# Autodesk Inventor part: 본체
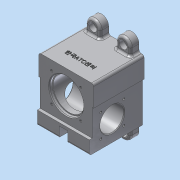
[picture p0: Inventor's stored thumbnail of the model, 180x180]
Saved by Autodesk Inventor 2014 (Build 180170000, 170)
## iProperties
Created: 2024-11
Part Number: 본체
Material: 알루미늄 6061
Document SubType Name: Modeling
Designer: dg
Density: 2.71 g/cm^3
Appearance: 알루미늄 - 평지
Mass: 806.366 g
Surface Area: 539.755 cm^2
Volume: 297.552 cm^3
Author: dg
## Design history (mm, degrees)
sketch "스케치1"
  geometry: L1 (-38, 0)-(38, 0); L2 (38, 0)-(38, -29); L3 (38, -29)-(36, -29); L4 (36, -29)-(36, -85); L5 (36, -85)-(6, -85); L6 (6, -85)-(6, -70); L7 (6, -70)-(-6, -70); L8 (-6, -70)-(-6, -85); L9 (-6, -85)-(-36, -85); L10 (-36, -85)-(-36, -29); L11 (-36, -29)-(-38, -29); L12 (-38, -29)-(-38, 0); 2 further points
  constraints: 24 end point, 10 parallel, 4 equal length, 1 coincident, 1 horizontal, 1 midpoint, 1 perpendicular
  dimensions: "d0" = 76 distance of L1.start L1.end; "d1" = 85 distance between parallel lines of L9 L1; "d2" = 56 distance of L9.end L10.end; "d3" = 15 distance of L7.end L8.end; "d4" = 12 distance of L6.end L7.end; "d5" = 2 distance of L10.end L11.end
extrude "돌출1" new body sketch "스케치1" distance "d6" = 74; taper "d7" = 0 deg
sketch "스케치2"
  geometry: L1 (0, 0)-(66, 0); L2 (66, 0)-(66, 4); L3 (66, 4)-(0, 4); L4 (0, 4)-(0, 0)
  constraints: 8 end point, 2 parallel, 1 horizontal, 1 perpendicular
  dimensions: "d8" = 4 distance of L1.end L2.end; "d9" = 66 distance of L2.end L3.end
extrude "돌출2" cut sketch "스케치2" stored distance "d10" = 74; taper "d11" = 0 deg
sketch "스케치3"
  geometry: L1 (-38, 0)-(38, 0) reference; L2 (36, 85)-(6, 85) reference; L3 (-6, 85)-(-36, 85) reference; L4 (-31, 85)-(-11, 85); L5 (-11, 85)-(-11, 105); L6 (-11, 105)-(-31, 105); L7 (-31, 105)-(-31, 85); L8 (11, 85)-(31, 85); L9 (31, 85)-(31, 105); L10 (31, 105)-(11, 105); L11 (11, 105)-(11, 85); L12 (-31, -20)-(-11, -20); L13 (-11, -20)-(-11, 0); L14 (-11, 0)-(-31, 0); L15 (-31, 0)-(-31, -20); L16 (11, -20)-(31, -20); L17 (31, -20)-(31, 0); L18 (31, 0)-(11, 0); L19 (11, 0)-(11, -20); 5 further points
  constraints: 32 end point, 8 parallel, 6 equal length, 6 midpoint, 4 horizontal, 4 perpendicular, 2 collinear, 2 point on line
  dimensions: "d12" = 20 distance of L5.end L6.end; "d13" = 20 distance of L6.end L4.start; "d14" = 62 distance between parallel lines of L9 L7; "d15" = 31 distance from line of point (0, 0) L7
extrude "돌출3" join sketch "스케치3" distance "d16" = 12; taper "d17" = 0 deg
fillet "모깎기1" dims "d18" = 10
sketch "스케치4" dims "d0" = 76, "d1" = 85, "d2" = 56, "d3" = 15, "d4" = 12, "d5" = 2
  geometry: L1 (0, 0)-(76, 0) reference; 2 further points
  constraints: 1 vertical alignment, 1 other
  dimensions: "d19" = 20 distance from line of point (38, 20) L1
feature "엠보싱1" sketch "스케치4" dims "d0" = 76, "d1" = 85, "d2" = 56, "d3" = 15, "d4" = 12, "d5" = 2, "d20" = 0.5, "d21" = 0
sketch "스케치5"
  geometry: L1 (4, -33)-(70, -33); L2 (4, -66)-(4, -29) reference; L3 (4, 0)-(74, 0) reference; L4 (4, -33)-(4, -9.5); L5 (4, -9.5)-(8, -9.5); L6 (8, -9.5)-(8, -11); L7 (8, -11)-(56, -11); L8 (56, -11)-(56, -15.5); L9 (56, -15.5)-(67, -15.5); L10 (67, -15.5)-(67, -18); L11 (67, -18)-(70, -18); L12 (70, -18)-(70, -33); L13 (0, -85)-(0, -70) reference; 1 further point
  constraints: 20 end point, 6 parallel, 3 perpendicular, 1 horizontal, 1 point on line
  dimensions: "d23" = 33 distance between parallel lines of L1 L3; "d24" = 66 distance of L1.start L1.end; "d25" = 47 diameter of L5 L1; "d26" = 44 diameter of L7 L1; "d27" = 35 diameter of L9 L1; "d28" = 30 diameter of L11 L1; "d29" = 4 distance of L4.end L5.end; "d30" = 56 distance between parallel lines of L13 L8; "d31" = 11 distance of L8.end L9.end
revolve "회전1" sketch "스케치5" stored, may be unused: angle "d32" = 90 deg
sketch "스케치6"
  geometry: L1 (-56, 74)-(0, 74) reference; L2 (-85, 4)-(-85, 74) reference; C1 r 16.5 at (-28, 32); 1 further point
  constraints: 1 centre point
  dimensions: "d33" = 57 distance from line of L2 C1.centre; "d34" = 42 distance from line of C1.centre L1; "d35" = 33 diameter of C1
extrude "돌출4" cut sketch "스케치6" stored distance "d36" = 12; taper "d37" = 0 deg
sketch "스케치7"
  geometry: C1 r 16.5 at (-28, 32) reference; 5 further points
  constraints: 2 horizontal alignment, 2 vertical alignment
  dimensions: "d38" = 32 distance of point (-12, 48) point (-44, 48); "d39" = 32 distance of point (-12, 16) point (-12, 48); "d40" = 16 horizontal distance of point (-12, 48) C1.centre; "d41" = 16 horizontal distance of C1.centre point (-12, 48)
hole "구멍1" sketch "스케치7" at (-44, 48), (-12, 48), (-44, 16), (-12, 16) diameter "d42" = 3.242; stored, may be unused: countersink angle "d46" = 90 deg, drill point angle "d48" = 118 deg; dims "d43" = 8, "d44" = 4, "d45" = 2, "d47" = 10
sketch "스케치8"
  geometry: C1 r 23.5 at (-38, -4) reference; A1 r 28.5 centre (-38, -4) between (-58.153, 16.153) and (-58.153, -24.153); 3 further points
  constraints: 4 point on circle, 2 horizontal alignment, 2 vertical alignment, 1 centre point, 1 coincident
  dimensions: "d49" = 57 diameter of A1; "d50" = 90 deg dimension on C1.centre point (-17.847, -24.153) point (-17.847, 16.153)
hole "구멍2" sketch "스케치8" at (-58.153, 16.153), (-58.153, -24.153), (-17.847, -24.153), (-17.847, 16.153) diameter "d51" = 3.242; stored, may be unused: countersink angle "d55" = 90 deg, drill point angle "d57" = 118 deg; dims "d52" = 8, "d53" = 4, "d54" = 2, "d56" = 10
hole "구멍3" diameter "d60" = 6.6; stored, may be unused: countersink angle "d64" = 90 deg, drill point angle "d66" = 0 deg; dims "d58" = 10, "d59" = 10, "d61" = 8, "d62" = 11, "d63" = 6.6, "d65" = 10
hole "구멍4" diameter "d69" = 6.6; stored, may be unused: countersink angle "d73" = 90 deg, drill point angle "d75" = 0 deg; dims "d67" = 10, "d68" = 10, "d70" = 8, "d71" = 11, "d72" = 6.6, "d74" = 10
hole "구멍5" diameter "d78" = 6.6; stored, may be unused: countersink angle "d82" = 90 deg, drill point angle "d84" = 0 deg; dims "d76" = 10, "d77" = 10, "d79" = 8, "d80" = 11, "d81" = 6.6, "d83" = 10
hole "구멍6" diameter "d87" = 6.6; stored, may be unused: countersink angle "d91" = 90 deg, drill point angle "d93" = 0 deg; dims "d85" = 10, "d86" = 10, "d88" = 8, "d89" = 11, "d90" = 6.6, "d92" = 10
sketch "스케치9"
  geometry: L1 (12, 0)-(0, 0) reference; 4 further points
  constraints: 2 vertical alignment, 1 midpoint
  dimensions: "d94" = 12 distance from line of point (6, 12) L1; "d95" = 40 distance of point (6, 52) point (6, 12)
hole "구멍7" sketch "스케치9" at (6, 12), (6, 52) diameter "d96" = 3.242; stored, may be unused: countersink angle "d100" = 90 deg, drill point angle "d102" = 118 deg; dims "d97" = 8, "d98" = 11, "d99" = 6.6, "d101" = 10
chamfer "모따기1" distance "d103" = 1; stored, may be unused: second distance "d104" = 2, angle "d105" = 45 deg
fillet "모깎기2" dims "d106" = 3
chamfer "모따기2" distance "d107" = 1; stored, may be unused: second distance "d108" = 2, angle "d109" = 45 deg
fillet "모깎기3" dims "d110" = 0.6
fillet "모깎기4" dims "d111" = 3
fillet "모깎기5" dims "d112" = 3
chamfer "모따기3" distance "d114" = 1; stored, may be unused: second distance "d115" = 2, angle "d116" = 45 deg
fillet "모깎기7" dims "d117" = 3
fillet "모깎기8" dims "d118" = 3
fillet "모깎기9" dims "d122" = 3
chamfer "모따기5" distance "d123" = 1; stored, may be unused: second distance "d124" = 2, angle "d125" = 45 deg
fillet "모깎기10" dims "d126" = 3
node "솔리드1"
mirror "대칭1"
